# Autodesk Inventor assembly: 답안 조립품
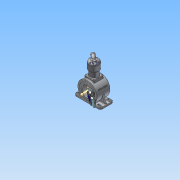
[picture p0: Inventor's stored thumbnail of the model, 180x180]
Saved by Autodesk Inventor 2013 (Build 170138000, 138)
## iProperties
Created: 2015-06
Part Number: 답안 조립품
Document SubType Name: Assembly
Designer: Administrator
Author: Administrator
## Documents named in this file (14)
- C:\Users\Administrator\Desktop\450606V1034\답안 조립품.iam
- C:\Users\Administrator\Desktop\450606V1034\답안 본체.ipt
- C:\Users\Administrator\Desktop\450606V1034\메인 크랭크 축-구동부.ipt
- C:\Users\Administrator\Desktop\450606V1034\메인커버.ipt
- C:\Users\Administrator\Desktop\450606V1034\베어링 6204.ipt
- C:\Users\Administrator\Desktop\450606V1034\베어링 NA 4902.ipt
- C:\Users\Administrator\Desktop\450606V1034\실린더.ipt
- C:\Users\Administrator\Desktop\450606V1034\실린더헤드.ipt
- C:\Users\Administrator\Desktop\450606V1034\오일실.ipt
- C:\Users\Administrator\Desktop\450606V1034\커넥팅 로드.ipt
- C:\Users\Administrator\Desktop\450606V1034\크랭크 서브축.ipt
- C:\Users\Administrator\Desktop\450606V1034\피스톤 핀.ipt
- C:\Users\Administrator\Desktop\450606V1034\피스톤.ipt
- C:\Users\Administrator\Desktop\450606V1034\M5x0.8.ipt
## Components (6 placed, 3 different names)
1. 피스톤 핀:1 — 플러쉬:1
2. 피스톤:1 — 플러쉬:1
3. M5x0.8:1
4. M5x0.8:2
5. M5x0.8:3
6. M5x0.8:4
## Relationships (1: Flush 1)
- 플러쉬:1 [Flush]: 피스톤 핀:1 ↔ 피스톤:1
